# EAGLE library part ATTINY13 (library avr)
MICROCONTROLLER 1 Kbytes FLASH 64 bytes EEPROM 64 bytes RAM 4-channel 10 bit ADC
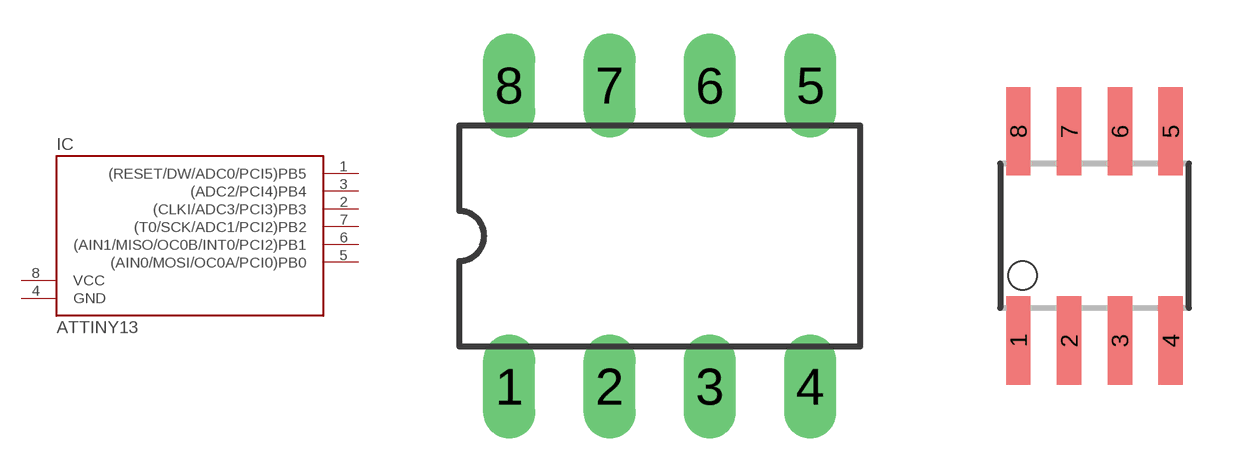
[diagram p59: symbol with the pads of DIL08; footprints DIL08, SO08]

Designator prefix IC

## ATTINY13-20P, ATTINY13V-10P  [DIL08]
1  (RESET/DW/ADC0/PCI5)PB5
2  (CLKI/ADC3/PCI3)PB3
3  (ADC2/PCI4)PB4
4  GND  pwr
5  (AIN0/MOSI/OC0A/PCI0)PB0
6  (AIN1/MISO/OC0B/INT0/PCI2)PB1
7  (T0/SCK/ADC1/PCI2)PB2
8  VCC  pwr

## ATTINY13-20SS, ATTINY13V-10SS  [SO08]
Pads as for DIL08

## ATTINY13-20S, ATTINY13V-10S  [SOIC8]
Pads as for DIL08

## Footprint DIL08 (pad centres in mm)
Dual In Line
drill 0.813 long: 1 -3.81,-3.81; 2 -1.27,-3.81; 3 1.27,-3.81; 4 3.81,-3.81; 5 3.81,3.81; 6 1.27,3.81; 7 -1.27,3.81; 8 -3.81,3.81

## Footprint SO08 (pad centres in mm)
Small Outline Package
smd 0.61 x 2.21: 1 -1.905,-2.616; 2 -0.635,-2.616; 3 0.635,-2.616; 4 1.905,-2.616; 5 1.905,2.616; 6 0.635,2.616; 7 -0.635,2.616; 8 -1.905,2.616

## Footprint SOIC8 (pad centres in mm)
Wide Plastic Gull Wing Small Outline Package
smd 0.5 x 2.2: 1 -1.905,-3.154; 2 -0.645,-3.154; 3 0.625,-3.154; 4 1.895,-3.154; 5 1.905,3.154; 6 0.635,3.154; 7 -0.635,3.154; 8 -1.905,3.154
